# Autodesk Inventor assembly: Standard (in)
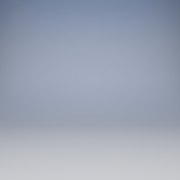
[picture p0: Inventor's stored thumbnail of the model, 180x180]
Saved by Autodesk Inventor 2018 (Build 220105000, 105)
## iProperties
Created: 2017-02
Part Number: Standard (in)
Material: Ogólny
Document SubType Name: Assembly
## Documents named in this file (1)
- C:\Users\Joffi\Desktop\Templates.Base\English.Base\Standard (in).iam
